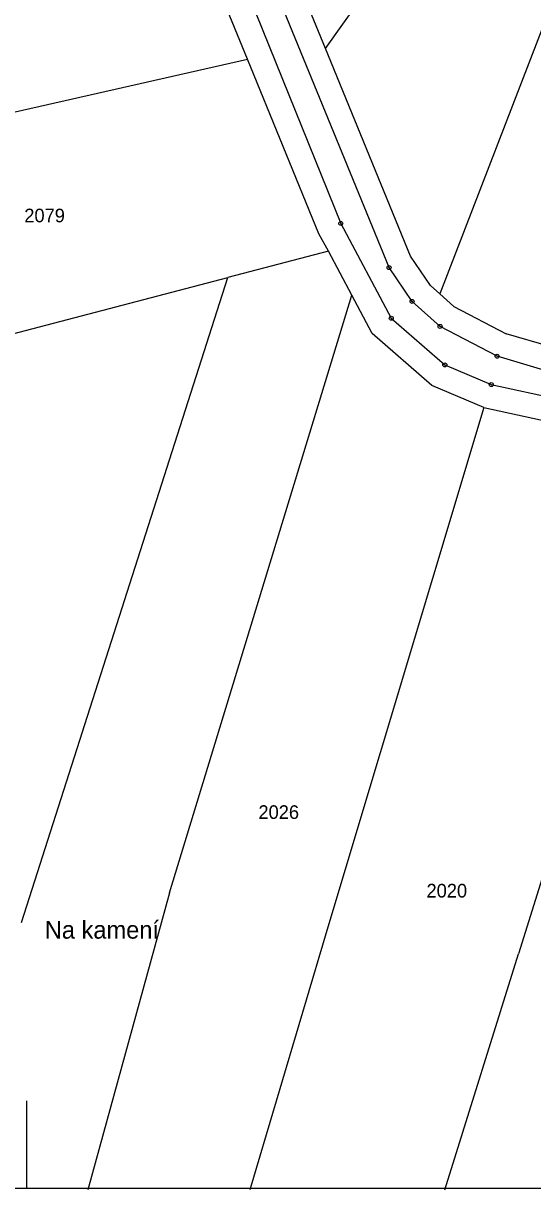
# Model space of a CAD drawing. Extents: x -566461 to -565198, y -1096301 to -1095707.
# Drawn here: x -566039.2 to -565912.3, y -1096301.3 to -1096010.8 of the extents above; entities that cross this region are included whole.
import ezdxf

# ---------------------------------------------------------------- set-up
doc = ezdxf.new("R2010")
doc.units = 0
for name, color, linetype in [('Vrstva 1', 7, 'Continuous'), ('Vrstva 15', 7, 'Continuous'), ('Vrstva 18', 7, 'Continuous'), ('Vrstva 24', 7, 'Continuous'), ('Vrstva 63', 7, 'Continuous')]:
    doc.layers.add(name, color=color, linetype=linetype)

msp = doc.modelspace()

# ---------------------------------------------------------------- linework, layer by layer
at = {"layer": 'Vrstva 1'}
for p, q in [((-565983.37, -1096019.72), (-566053.24, -1095848.98)), ((-565963.96, -1096017.08), (-565993.59, -1095944.66)), ((-565963.96, -1096017.08), (-565914.03, -1095946.48)), ((-566005.23, -1095949.18), (-565960.14, -1096060.64)), ((-565948.12, -1096071.63), (-565999.14, -1095946.93)), ((-565887.08, -1095952.89), (-565935.5, -1096078.14)), ((-565942.81, -1096068.77), (-565963.96, -1096017.08)), ((-566099.43, -1096046), (-565983.37, -1096019.72)), ((-565965.58, -1096063.19), (-565983.37, -1096019.72)), ((-565960.14, -1096060.64), (-565947.56, -1096084.25)), ((-565963.24, -1096067.58), (-565965.58, -1096063.19)), ((-565963.24, -1096067.58), (-565988.25, -1096074.11)), ((-565957.4, -1096078.54), (-565963.24, -1096067.58)), ((-565937.82, -1096076.07), (-565942.81, -1096068.77)), ((-566049.51, -1096090.1), (-565988.25, -1096074.11)), ((-566039.72, -1096234.72), (-565988.25, -1096074.11)), ((-565942.36, -1096080.06), (-565948.12, -1096071.63)), ((-565937.82, -1096076.07), (-565935.5, -1096078.14)), ((-566002.86, -1096227.33), (-565957.4, -1096078.54)), ((-565952.33, -1096088.05), (-565957.4, -1096078.54)), ((-565935.41, -1096086.27), (-565942.36, -1096080.06)), ((-565935.5, -1096078.14), (-565931.97, -1096081.29)), ((-565931.97, -1096081.29), (-565918.93, -1096088.11)), ((-565947.56, -1096084.25), (-565934.22, -1096095.86)), ((-565937.44, -1096101.01), (-565952.33, -1096088.05)), ((-565921.19, -1096093.7), (-565935.41, -1096086.27)), ((-565908.08, -1096091.32), (-565918.93, -1096088.11)), ((-565909.52, -1096097.15), (-565921.19, -1096093.7)), ((-565934.22, -1096095.86), (-565922.65, -1096100.77)), ((-565924.47, -1096106.51), (-565937.44, -1096101.01)), ((-565922.65, -1096100.77), (-565855.22, -1096115.35)), ((-565924.47, -1096106.51), (-565963.09, -1096235.11)), ((-565924.47, -1096106.51), (-565876.67, -1096116.85)), ((-565876.67, -1096116.85), (-565915.86, -1096242.54)), ((-566002.86, -1096227.33), (-566023.14, -1096301.3)), ((-565963.09, -1096235.11), (-565982.78, -1096301.3)), ((-565934.18, -1096301.3), (-565915.86, -1096242.54))]:
    msp.add_line(p, q, dxfattribs=at)
at = {"layer": 'Vrstva 24'}
for centre, radius in [((-565960.14, -1096060.64), 0.5), ((-565960.14, -1096060.64), 0.0327), ((-565948.12, -1096071.63), 0.5), ((-565948.12, -1096071.63), 0.0327), ((-565942.36, -1096080.06), 0.5), ((-565942.36, -1096080.06), 0.0327), ((-565947.56, -1096084.25), 0.5), ((-565947.56, -1096084.25), 0.0327), ((-565935.41, -1096086.27), 0.5), ((-565935.41, -1096086.27), 0.0327), ((-565921.19, -1096093.7), 0.5), ((-565921.19, -1096093.7), 0.0327), ((-565934.22, -1096095.86), 0.5), ((-565934.22, -1096095.86), 0.0327), ((-565922.65, -1096100.77), 0.5), ((-565922.65, -1096100.77), 0.0327)]:
    msp.add_circle(centre, radius, dxfattribs=at)
at = {"layer": 'Vrstva 63'}
for p, q in [((-566038.38, -1096301.03), (-566038.38, -1096279.18)), ((-565198.38, -1096301.03), (-566458.38, -1096301.03))]:
    msp.add_line(p, q, dxfattribs=at)

# ---------------------------------------------------------------- texts
at = {"layer": 'Vrstva 15'}
msp.add_text('Na kamení', height=4.4, dxfattribs=at).set_placement((-566033.89, -1096238.78))
at = {"layer": 'Vrstva 18'}
for s, p in [('2079', (-566039, -1096060.36)), ('2026', (-565980.66, -1096208.96)), ('2020', (-565938.78, -1096228.53))]:
    msp.add_text(s, height=3.4, dxfattribs=at).set_placement(p)

doc.saveas('drawing.dxf')
